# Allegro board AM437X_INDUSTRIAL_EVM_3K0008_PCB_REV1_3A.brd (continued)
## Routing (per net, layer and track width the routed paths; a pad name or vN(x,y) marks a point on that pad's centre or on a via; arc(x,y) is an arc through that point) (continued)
VDD_CORE: length 131.7
  TOP w0.203: v1(84.79,65.6) 84.79,66.09 U11.W12 U11.W13
  TOP w0.254: U11.N16 U11.N17 U11.P17 81.13,69.75 v1(81.61,69.27) 81.44,69.1 U11.P16 ; U11.M14 U11.L14 79.19,67.5 v1(79.36,67.32) ; v1(79.36,65.37) 79.36,65.02 U11.M9 U11.N9 ; U11.M12 U11.L12 78.85,66.83 v1(78.85,66.89) ; v1(82.61,65.37) 82.61,65.68 U11.T11 U11.R11 ; U11.R14 81.78,67.74 v1(82.13,67.39) 82.43,67.7 U11.T14 U11.U15 U11.V15 ; U11.R9 81.78,64.69 v1(82.11,65.02) 82.43,64.69 U11.T9 ; U11.T18 U11.T19 82.23,71.05 v1(82,71.28) ; U11.J11 77.89,65.85 v1(78.36,65.37) 78.19,65.2 U11.J10
  TOP w0.508: v3(107.53,64.23) R139.2 v3(106.53,65.28)
  L5_PWR w0.508: v1(79.36,67.32) 78.93,66.89 v1(78.85,66.89)
  BOTTOM w0.381: C213.1 80.23,68.37 79.55,67.69 79.55,67.51 v1(79.36,67.32) ; C221.1 84.79,66.46 v1(84.79,65.6) 84.84,65.56 84.84,65.48 85.55,64.77 85.72,64.77 ; C202.1 82.77,71.28 v1(82,71.28) ; v1(82.61,65.37) 82.61,66.04 C224.1 ; v1(78.36,65.37) 78.36,65.78 C219.1 ; v1(78.85,66.89) 79.36,66.39 C220.1
  BOTTOM w0.508: v1(81.61,69.27) 81.61,69.27 C205.1 ; v3(94.2,56.64) 95.14,56.64 C257.1 94.63,57.66 v3(94.23,57.66)
  BOTTOM w0.762: v3(106.53,65.28) 105.35,64.1 105.35,60.39 105.79,59.94 105.79,54.74 104.9,53.85 104.9,50.67 v4(106.3,49.28) ; v4(106.33,45.72) 106.33,41.53 107.82,40.04 107.82,22.23 102.23,16.64 102.23,13.55 100.49,11.81 91.95,11.81 90.07,13.69 88.87,13.69 87.86,12.67 73.24,12.67 70.93,14.99 v3(58.12,14.99) v3(56.95,14.99)
  vias: v4(104.52,49.28) v4(104.52,47.5) v4(104.55,45.72) v4(106.3,47.5)
VDD_CORE_EN: length 86.1
  TOP w0.13: v1(107.95,43.81) 107.95,20.37 106.12,18.54 v1(106.08,18.54) ; R234.1 67.57,11.05 v1(66.67,11.95) U26.17
  L3_SIG1 w0.13: v1(107.95,43.81) 107.95,43.94 108.83,44.82 111.88,44.82 v1(115.19,48.13)
  BOTTOM w0.13: v1(115.19,48.13) 115.19,49.78 R482.2 ; v1(106.08,18.54) 103.96,16.42 103.96,14.11 100.79,10.94 98.51,10.94 97.68,10.11 91.01,10.11 89.47,11.65 83.22,11.65 81.68,10.11 72.29,10.11 70.45,11.95 v1(66.67,11.95)
VDD_COREREG: length 4.8
  BOTTOM w0.203: 115.82,46.36 U53.A2 U53.B2 115.82,46.86
VDD_MPU: length 141.2
  TOP w0.203: U11.M18 79.55,70.68 79.55,71.28
  TOP w0.254: v1(78.36,67.32) 78.19,67.15 U11.J13 U11.J14 U11.H14 U11.H13 ; v1(78.06,71.73) 78.51,71.73 U11.K20 U11.L20 79.2,71.7 v1(79.59,71.31) 79.32,71.05 U11.L19 U11.K19 ; U11.M17 U11.M18 ; U11.H16 U11.J16 78.19,69.1 v1(78.37,68.93)
  TOP w0.508: R230.2 56.78,11.68 55.98,12.48 55.98,17.31 58.49,19.81 63.37,19.81 64.64,21.08 64.64,23.8 64.19,24.25 64.19,25.73 v3(64.69,26.24)
  L3_SIG1 w0.508: v3(64.69,26.24) 67.26,23.67 67.26,23.67 69.59,21.34 72.01,21.34 72.95,22.28 73.82,22.28 74.83,21.26 75.72,21.26 76.79,20.19 77.24,20.19 77.42,20.02 78.72,20.02 80.06,18.67 82.99,18.67 84.21,19.89 93.17,19.89 93.47,20.19 93.47,21.37 96.49,24.38 96.74,24.64 96.74,24.64 96.87,24.77 99.95,24.77 102.2,27.02 102.2,32.48 101.46,33.23 101.46,38.45 100.81,39.09 100.81,50 96.46,54.36 95.17,54.36 93.28,56.24 93.28,58.23 91.47,60.05 89.92,60.05 88.87,61.09 88.87,61.57 85.65,64.79 83.87,64.79 83.44,65.23 83.44,67.46 82.72,68.18 78.92,68.18 78.36,67.62 v1(78.36,67.32)
  L5_PWR w0.508: 94.7,82.76 TP7.1 96.31,82.76
  BOTTOM w0.381: C197.1 78.59,72.1 78.22,71.73 v1(78.06,71.73) ; C203.1 79.21,71.31 v1(79.59,71.31) ; v1(78.37,68.93) 78.37,69.1 77.87,69.6 C207.1
  BOTTOM w0.508: v3(88.75,82.6) 88.75,83.48 C172.1 87.91,83.35 v3(87.91,82.63)
  vias: v3(64.82,27.13) v4(93.85,87.5) v4(93.85,85.72) v4(95.5,85.72) v4(97.16,87.5) v4(97.16,85.72)
VDD_MPU_EN: length 203.1
  TOP w0.13: U26.18 66.12,12.45 67.01,13.34 R228.1 67.69,13.27 68.39,12.57 69.04,12.57 69.55,13.08 v1(69.93,13.08) ; v1(104.23,98.14) v1(104.23,105.12)
  L3_SIG1 w0.13: v1(136.91,52.45) 136.91,50.72 136.58,50.4 136.58,40.82 131.84,36.08 127.43,36.08 124.12,39.38 121.22,39.38 120.76,38.93 120.76,36 119.87,35.11 119.87,34.28 119,33.42 117.66,33.42 117.21,32.96 117.21,31.9 110.33,25.02 110.33,23.13 108.12,20.92 108.12,17.97 104.41,14.26 104.41,11.37 102.61,9.57 100.37,9.57 100.04,9.24 96.31,9.24 95.66,8.59 91.51,8.59 90.85,9.25 78.51,9.25 74.93,12.83 70.18,12.83 v1(69.93,13.08) ; v1(104.23,105.12) 104.9,105.79 117.23,105.79 117.62,106.18 121.34,106.18 122.1,106.93 129.16,106.93 131.19,104.9 131.19,103.84 136.03,99 136.03,94.61 136.46,94.18 136.46,89.88 134.4,87.83 134.4,87.21 134.67,86.94 134.67,86.1 136.27,84.5 v1(136.27,73.53)
  L4_SIG2 w0.13: v1(136.27,73.53) 136.27,73.15 135.36,72.24 135.36,70.55 136.4,69.52 136.4,58.85 137.19,58.06 137.19,52.73 v1(136.91,52.45)
  BOTTOM w0.13: R324.2 v1(104.23,98.14)
VDD_MPU_OUT: length 2.3
  BOTTOM w0.254: U35.B3 U35.B4 100.71,93.43
  BOTTOM w0.381: 99.41,93.57 99.54,93.43 100.71,93.43
VDD_MPU_SENSE: length 2.5
  TOP w0.508: R52.1 96.77,90.68 v3(97.28,90.17)
VDD_MPU_SENSEP: length 7.7
  TOP w0.508: v1(103.59,93.43) 96.81,93.43 R52.2
  BOTTOM w0.254: 103,93.43 U35.B1
  BOTTOM w0.381: v1(103.59,93.43) 103,93.43
VDD_TAMPER: length 17.7
  TOP w0.13: U11.AD9 87.94,64.86 88.73,64.86
  TOP w0.508: R139.1 104.48,63.97 C60.1 96.07,63.97 95.42,64.63 90.17,64.63 89.94,64.86 88.73,64.86
VDDA1P8_PMLDO: length 3.7
  TOP w0.254: U11.D6 v1(74.48,62.11)
  BOTTOM w0.381: v1(74.48,62.11) 74.03,62.11 74.03,62.11 73.54,62.11 73.28,61.85 R463.1
VDDA3P3_PMLDO: length 5.5
  TOP w0.254: v1(75.93,64.38) 75.94,64.38 U11.F8
  BOTTOM w0.381: R456.1 71.96,63.81 75.25,63.81 75.62,64.19 75.63,64.19 75.83,64.38 v1(75.93,64.38)
VDDA_ADC: length 13
  TOP w0.254: v1(86.65,65.59) 86.65,66.19 U11.AB12
  BOTTOM w0.508: 88.04,67.15 88.04,66.33 87.31,65.59 v1(86.65,65.59) ; 88.04,67.15 93.25,67.15 94.74,65.66 FB14.1 ; 88.04,67.15 88.01,67.18
VDDA_MC_ADC: length 19.5
  TOP w0.13: v1(84.7,69.45) 84.7,69.43 84.74,69.39 84.74,69.39 U11.Y16
  L3_SIG1 w0.254: 89.03,69.6 88.14,68.71 85.41,68.71 84.7,69.42 v1(84.7,69.45)
  L3_SIG1 w0.508: 89.03,69.6 89.66,70.23 94.74,70.23 95.89,71.37 100.86,71.37 v3(101.32,71.83)
  BOTTOM w0.381: v1(84.7,69.45) 84.81,69.34 84.81,69.22 85.14,68.89 C211.1
VDDR_VREF: length 58.2
  TOP w0.203: U20.M8 76.06,31.61 75.69,31.24 75.07,31.24 74.69,30.86 74.32,30.86 v1(73.85,30.4)
  TOP w0.254: U21.M8 v1(94.33,31.22)
  TOP w0.305: U25.6 92.1,12.6
  TOP w0.381: U21.H1 87.65,34.82 87.18,34.34 v1(87.18,32.87) ; U20.H1 69.98,34.82
  TOP w0.508: 69.98,34.82 69.49,34.82 v1(69.09,34.42) v1(68.58,33.91)
  L4_SIG2 w0.508: 95.38,26.8 95.38,25.91 92.2,22.73 82.22,22.73 81.58,23.37 80.98,23.37 80.34,22.73 78.89,22.73 v3(78.18,23.44) v3(76.96,23.44)
  BOTTOM w0.508: v1(87.18,32.87) 86.43,32.13 C311.1 86.3,32.07 86.3,31.79 85.36,30.85 ; C317.2 94.33,30.51 v1(94.33,31.22) 94.33,31.97 C312.1 ; C330.1 73.85,27.21 v1(73.85,30.4) ; v1(68.58,33.91) 68.2,33.53 C307.1 C313.2
  BOTTOM w0.762: 74.42,25.91 70.99,25.91 69.39,27.51 ; 75.18,27.05 79.76,27.05 83.55,30.85 85.36,30.85
VDDR_VTT: length 9.5
  TOP w0.254: U25.3 93.85,16.76 C106.1
  TOP w0.508: R225.2 88.65,16.89 88.14,17.4 88.14,21.35 v3(88.15,21.36) ; C106.1 93.34,18.53 C104.1
  vias: v3(85.61,21.41) v3(86.89,21.36) v3(89.64,21.32) v3(90.92,21.32) v3(92.08,21.34)
VDDS_CTM: length 9.6
  TOP w0.13: 88.79,66.18 87.96,66.18 U11.AD12
  TOP w0.508: 88.79,66.18 89.31,65.66 FB6.1
VDDS_DDR: length 89.9
  TOP w0.203: v1(70.86,32.83) 70.88,32.83 U20.K2
  TOP w0.254: v1(69.73,29.37) 70,29.11 70.35,29.11 U20.R1 ; v1(88.62,39.19) 88.75,39.19 U21.C1 89.28,38.66 89.28,38.44 89.7,38.02 U21.D2 ; v1(96.27,34.42) 95.87,34.82 U21.H9 ; v1(76.43,33.58) 76.41,33.58 76.06,33.23 U20.K8 ; U20.R9 77.21,29.22 77.41,29.41 v1(77.44,29.41) ; v1(69.91,30.91) 70.37,30.91 U20.N1 ; U21.E9 95.65,37.33 95.98,37.33 v1(96.09,37.44) ; U20.E9 77.3,37.22 v1(77.36,37.16) ; U20.F1 70.34,36.3 69.91,36.3 69.85,36.36 v1(69.84,36.36) ; U21.F1 v1(88.62,36.42) ; U21.D9 95.98,38.02 v1(96.08,38.12) ; U21.A8 v1(95.13,40.82) ; U21.A1 v1(88.62,40.42) ; U20.H2 v1(70.86,34.42) ; v1(76.05,40.95) 76.06,40.93 U20.A8 ; U21.G7 v1(93.29,35.62) ; v1(96.07,28.47) 96.07,28.68 U21.R9 ; v1(76.44,39.26) 76.44,39.24 U20.C9 ; U20.G7 74.92,35.27 74.92,35.18 v1(74.85,35.12) ; U21.K2 89.97,33.22 90.31,32.88 v1(90.31,32.88) ; C107.1 94.35,16.88 U25.2 ; v1(69.66,38.96) 69.81,38.82 U20.C1 70.46,38.63 71.08,38.02 U20.D2 ; U20.B2 70.92,39.95 70.85,39.95 v1(70.85,39.96) ; U20.N9 76.94,30.82 77.03,30.91 77.73,30.91 v1(78.08,31.27) ; U21.B2 v1(90.33,40.02) ; U21.N9 95.64,30.71 v1(96.42,30.71) ; v1(77.36,37.96) 77.3,38.02 U20.D9 ; v1(89.62,35.21) 89.62,35.13 U21.H2 ; U20.A1 v1(70.46,40.98) ; U21.C9 v1(96.72,38.82) ; v1(77.37,34.82) 77.37,34.82 U20.H9 ; U21.K8 v1(94.33,32.82)
  TOP w0.381: v3(65.37,44.58) 65.37,44.18
  TOP w0.457: 65.37,44.18 65.91,43.63
  TOP w0.508: 65.91,43.63 C80.1 64.88,43.16 v3(63.9,42.18) ; v3(95.63,20.32) 98.3,20.32 99.06,19.56 99.06,15.49 98.17,14.61 R226.2 C111.1 ; v3(82.68,23.93) C102.1 v3(81.28,22.59)
  L3_SIG1 w0.508: 76.07,32.77 75.66,32.35 72.33,32.35 71.84,32.83 v1(70.86,32.83) ; v1(78.08,31.27) 78.08,32.03 77.98,32.13
  L4_SIG2 w0.508: v1(77.44,29.41) 78.08,30.05 v1(78.08,31.27)
  BOTTOM w0.381: C302.1 70.86,35.06 v1(70.86,34.42) ; v1(74.85,35.12) 75.06,35.32 C299.1 ; v1(96.27,34.42) 96.14,34.54 C301.1 ; C317.1 95.76,30.48 95.99,30.71 v1(96.42,30.71) 96.58,30.86 C318.1 ; v1(88.62,28.3) 88.73,28.3 88.95,28.51 89.09,28.51 C328.1 ; C283.1 88.34,40.64 88.56,40.42 v1(88.62,40.42) ; v1(77.36,37.96) 77.1,37.96 76.71,38.35 C288.1 ; C285.1 76,39.61 76.34,39.26 v1(76.44,39.26) ; 69.09,30.86 69.14,30.91 v1(69.91,30.91) ; v1(96.09,37.44) 96.09,37.32 96.45,36.96 C296.1 ; C292.1 70.09,38.24 70.09,38.27 69.66,38.7 v1(69.66,38.96) 69.33,38.96 69.3,38.99 68.71,38.99 ; v1(69.73,29.37) 69.67,29.31 69.12,29.31 C324.1 ; v1(69.84,36.36) 69.78,36.3 69.7,36.3 69.22,35.81 C297.1 ; C294.1 89.43,36.42 v1(88.62,36.42)
  BOTTOM w0.508: C279.1 68.73,41.27 68.82,41.18 70.26,41.18 v1(70.46,40.98) ; C313.1 68.58,30.86 69.09,30.86 ; C329.1 96.39,27.3 96.39,27.81 96.07,28.14 v1(96.07,28.47) ; v1(77.36,37.16) 77.08,36.88 C295.1 ; v1(95.13,40.82) 94.83,40.51 C284.1 ; C318.1 97.69,31.39 100.74,31.39 101.85,32.51 C306.2 ; C290.1 95.49,38.12 v1(96.08,38.12) 96.76,38.12 C291.1 ; C277.1 75.95,41.05 v1(76.05,40.95) ; C282.1 96.9,39.43 96.72,39.25 v1(96.72,38.82) ; C323.1 77.55,29.34 77.47,29.41 v1(77.44,29.41) ; C316.1 87.79,30.1 88.28,30.58 88.28,30.6 v1(88.27,30.61) ; C314.1 90.3,32.26 90.3,32.87 v1(90.31,32.88) ; v1(70.86,34.42) v1(70.86,32.83) 70.84,32.83 69.77,33.91 C304.1 ; C278.1 90.17,40.18 v1(90.33,40.02)
  vias: v3(64.01,38.86) v3(64.01,37.59) v3(64.01,36.32) v3(64.01,35.05) v3(65.28,38.86) v3(65.28,37.59) v3(65.28,36.32) v3(65.28,35.05) v3(94.61,21.21) v3(94.61,20.19) v3(95.63,21.21)
VDDS_TAMPER: length 17.6
  TOP w0.13: 88.9,63.59 87.94,63.59 U11.AD8
  TOP w0.508: 88.9,63.59 95.19,63.59 95.95,62.83 C62.1 104.48,62.83 R142.1
ADC0_VREFP: length 11.7
  TOP w0.13: U11.AD14 87.94,67.49 89.99,67.49 90.55,66.93 94.4,66.93 95.44,67.96 95.78,67.96 C56.1 C57.1 R126.2
ADC1_VREFP: length 13.8
  TOP w0.13: U11.AE15 93.88,68.45 95.54,70.11 95.92,70.11 96.98,71.16 97.62,71.16 C54.1 C55.1 R110.2
AM437X_AIN0: length 66.2
  TOP w0.13: v1(108.97,75.18) 109.62,74.53 109.62,73.37 109.09,72.84 108.83,72.84 107.98,71.99 107.98,68.83 105.25,66.11 103.32,66.11 v1(103.25,66.04)
  L4_SIG2 w0.13: v1(108.97,75.18) 106.2,75.18 105.5,75.89 105.5,77.81 105.95,78.26 105.95,80.91 106.71,81.67 110.48,81.67 111.05,82.24 112.15,82.24 112.47,82.55 112.47,86.35 111.81,87.01 111.81,89.06 110.72,90.14 110.72,91.07 109.27,92.53 108.23,92.53 106.87,93.89 106.87,101.31 108.33,102.77 108.33,109.05 108.89,109.61 108.89,111.23 107.82,112.29 J1.31
  BOTTOM w0.13: R450.1 v1(103.25,66.04)
AM437X_AIN1: length 62.1
  BOTTOM w0.13: J1.33 113.14,111.46 118.34,111.46 119.25,110.54 119.25,109.58 119.43,109.4 119.43,106.61 119.1,106.28 119.1,105.39 118.11,104.4 118.11,97.95 116.97,96.8 116.97,93.22 116.33,92.58 112.95,92.58 111.28,90.91 111.28,88.77 110.52,88.01 109.78,88.01 107.54,85.77 107.54,83.11 108.74,81.91 109.98,81.91 110.84,81.05 110.84,75.92 110.54,75.62 110.54,71.36 109.55,70.36 R440.1
AM437X_AIN2: length 50.4
  L3_SIG1 w0.13: v1(106.4,74.17) 105.41,75.16 105.41,79.02 106.48,80.09 v1(107.29,80.09)
  L4_SIG2 w0.13: J1.35 112.9,112.74 111.49,111.33 111.49,109.46 110.84,108.81 110.84,103.63 110.54,103.33 110.54,98.27 110.26,97.99 110.26,94.47 111.65,93.08 111.65,90.52 112.73,89.44 112.73,87.39 113.39,86.73 113.39,81.13 112.79,80.53 107.74,80.53 v1(107.29,80.09)
  BOTTOM w0.13: 107.06,73.91 106.81,74.17 v1(106.4,74.17)
AM437X_AIN3: length 52.6
  L3_SIG1 w0.13: v2(106.3,72.77) 107.19,73.66 107.19,76.42 105.83,77.78 105.83,78.36 107.07,79.6 109.02,79.6 109.25,79.38 v1(109.93,79.38)
  L4_SIG2 w0.13: v1(109.93,79.38) 112.78,79.38 114.23,80.83 114.23,86.76 113.35,87.65 113.35,89.46 113.67,89.78 113.67,90.42 113.37,90.72 113.37,94.53 112.83,95.07 112.83,99.46 112.42,99.88 112.42,107.08 114.09,108.76 114.09,110.92 115.44,112.27 J1.37
  BOTTOM w0.13: 107.06,72.77 v2(106.3,72.77)
AM437X_AIN4: length 55.1
  TOP w0.13: v1(105.94,76.5) 105.94,76.16 105.66,75.88 105.66,72.64 105.92,72.39 105.92,71.75 105.28,71.12
  L4_SIG2 w0.13: J1.32 109.01,115.59 109.01,112 109.3,111.71 109.3,109.57 108.64,108.92 108.64,102.64 108.36,102.36 108.36,96.32 108.47,96.21 108.47,93.76 111.03,91.2 111.03,90.27 112.11,89.19 112.11,87.14 112.78,86.47 112.78,82.42 112.28,81.93 111.17,81.93 110.6,81.36 106.84,81.36 106.26,80.78 106.26,79.63 106.74,79.15 106.74,78.1 106.79,78.05 106.79,77.36 v1(105.94,76.5)
AM437X_AIN5: length 53.8
  TOP w0.13: v1(106.71,80.59) 106.71,79.2 105.28,77.77 105.28,72.14 ; v1(110.23,107.95) 109.32,108.86 109.32,110.54 109.32,110.54 109.32,115.73 J1.34
  L4_SIG2 w0.13: v1(106.71,80.59) 107.02,80.91 112.53,80.91 113.08,81.46 113.08,86.6 112.42,87.26 112.42,89.31 111.34,90.39 111.34,91.76 109.95,93.15 109.95,98.53 109.37,99.11 109.37,101.88 110.23,102.73 v1(110.23,107.95)
AM437X_AIN6: length 61.4
  TOP w0.13: v1(108.03,80.09) 108.46,79.65 108.46,78.87 107.5,77.91 107.5,76.01 109.31,74.2 109.31,73.5 108.96,73.15 108.66,73.15 107.59,72.09 107.59,68.89 106.02,67.31 105.28,67.31
  L4_SIG2 w0.13: v1(108.03,80.09) 112.98,80.09 113.7,80.81 113.7,86.86 113.04,87.52 113.04,89.57 112.75,89.86 112.75,90.23 113.03,90.51 113.03,94 110.85,96.18 110.85,103.21 111.15,103.51 111.15,108.68 111.86,109.39 111.86,111.26 113.88,113.28 113.88,115.79 J1.36
AM437X_AIN7: length 58
  TOP w0.13: 105.28,68.58 105.98,69.28 106.23,69.28 106.49,69.54 106.49,70.5 106.75,70.76 106.75,72.55 107,72.8 107,76.01 106.81,76.2 106.81,77.9 v1(107.19,78.28)
  L4_SIG2 w0.13: v1(107.19,78.28) 107.65,78.28 108.19,78.83 112.74,78.83 114.54,80.63 114.54,91.98 114.37,92.16 114.37,93.98 113.14,95.2 113.14,99.59 112.72,100.01 112.72,106.93 114.4,108.61 114.4,110.78 116.42,112.8 116.42,115.79 J1.38
AM437X_CAM0_DATA0: length 145.3
  TOP w0.13: v1(97.97,78) 96.59,76.62 96.59,73.98 95.12,72.52 95.12,72.23 93.29,70.4 U11.AE18 ; v1(122.55,9.4) R264.2
  L3_SIG1 w0.13: v1(114.35,95.17) 111.51,92.33 109.35,92.33 108.77,91.75 108.77,89.63 109.63,88.77 109.63,87.87 104.79,83.04 104.63,83.04 104.07,83.59 103.91,83.59 103.8,83.48 103.8,83.32 104.35,82.76 104.35,82.6 104.24,82.48 104.08,82.48 103.52,83.04 103.36,83.04 103.24,82.92 103.24,82.76 103.8,82.21 103.8,82.05 103.68,81.93 103.52,81.93 102.97,82.49 102.81,82.49 102.69,82.37 102.69,82.21 103.25,81.65 103.25,81.49 103.13,81.38 102.97,81.38 102.41,81.93 102.25,81.93 102.14,81.82 102.14,81.66 102.69,81.1 102.69,80.94 101.38,79.63 101.38,79.28 100.83,78.73 98.7,78.73 v1(97.97,78)
  L4_SIG2 w0.13: v1(122.55,9.4) 122.08,9.87 120.33,9.87 119,8.54 115.28,8.54 111.56,12.26 111.56,16.53 112.69,17.65 114.06,17.65 115.32,18.91 115.32,24.18 117.22,26.08 117.22,28.55 117.22,28.55 117.22,29.68 117.22,29.68 117.22,33.7 116.97,33.95 116.11,34.81 116.11,38.1 114.83,39.37 114.83,44.26 114.48,44.62 114.48,50.65 114.65,50.82 114.65,51.89 113.68,52.85 113.68,55.8 114.35,56.46 114.35,59.38 110.41,63.32 108.25,63.32 107.87,63.71 106.68,63.71 106.2,64.19 105.5,64.88 103.74,64.88 100.76,67.87 100.3,67.87 99.69,68.48 99.69,69.39 100,69.7 100,74.29 99.46,74.84 99.46,76.51 v1(97.97,78)
  BOTTOM w0.13: R326.2 114.68,95.5 v1(114.35,95.17)
AM437X_CAM0_DATA1: length 192.3
  TOP w0.13: U11.AB18 v1(86.33,69.93) ; v1(112.14,12.57) 107.06,12.57 105.28,10.79 R253.2
  L3_SIG1 w0.13: v1(86.33,69.93) 89.18,72.77 91.28,72.77 92.18,73.67 93.5,73.67 95.47,75.63 95.47,80.25 96.58,81.37 97.62,81.37 98.17,81.91 100.71,81.91 101.2,82.41 101.2,82.57 100.92,82.85 100.92,83.01 101.04,83.13 101.2,83.13 101.48,82.85 101.64,82.85 101.76,82.96 101.76,83.12 101.47,83.41 101.47,83.57 101.59,83.68 101.75,83.68 102.03,83.4 102.2,83.4 107.09,88.29 v1(109.12,88.29)
  L4_SIG2 w0.13: v1(112.14,12.57) 113.47,13.9 116.53,13.9 121.88,19.26 121.88,26.39 125.53,30.03 125.53,39.04 124.55,40.02 124.55,45.16 124.19,45.52 124.19,47.5 125.85,49.16 125.85,58.75 123.11,61.49 123.11,65.54 119.27,69.38 116.11,69.38 113.61,71.88 v1(109.86,71.88)
  BOTTOM w0.13: R375.2 90.55,97.03 93.83,100.3 95.99,100.3 98.81,103.12 102.23,103.12 105.03,100.33 108.77,100.33 109.35,99.75 109.35,98.55 111.39,96.51 R327.2 112.9,93.15 110.57,90.81 110.57,89.39 109.89,88.71 109.54,88.71 v1(109.12,88.29) 109.12,87.97 107.1,85.95 107.1,82.91 108.56,81.46 109.68,81.46 110.41,80.73 110.41,76.1 110.11,75.8 110.11,72.14 v1(109.86,71.88)
AM437X_CAM0_DATA2: length 55.3
  TOP w0.13: v1(85.06,69.93) 85.03,69.95 U11.Y18 ; v1(113.23,101.73) 113.85,101.12 U6.5
  L3_SIG1 w0.13: v1(113.23,101.73) 112.98,101.47 108.33,101.47 102.87,96.01 102.87,93.6 102.72,93.45 102.39,93.45 102.23,93.3 102.23,93.08 102.39,92.93 102.72,92.93 102.87,92.77 102.87,92.56 102.72,92.41 102.39,92.41 102.23,92.25 102.23,92.04 102.39,91.88 102.72,91.88 102.87,91.73 102.87,91.52 102.72,91.36 102.39,91.36 102.23,91.21 102.23,90.99 102.39,90.84 102.72,90.84 102.87,90.69 102.87,89.92 96.61,83.66 96.61,82.63 94.55,80.57 94.55,75.95 93.16,74.56 91.84,74.56 91.07,73.79 88.91,73.79 v1(85.06,69.93)
AM437X_CAM0_DATA3: length 55.7
  TOP w0.13: v1(85.68,69.93) U11.AA18 ; U6.6 v1(113.2,100.2)
  L3_SIG1 w0.13: v1(113.2,100.2) 112.56,100.84 108.31,100.84 106.68,99.21 106.68,95.38 105.79,94.49 105.25,94.49 104.27,93.5 104.27,90.68 103.93,90.34 103.93,90.12 104.46,89.59 104.46,89.37 104.31,89.22 104.09,89.22 103.56,89.75 103.34,89.75 103.19,89.6 103.19,89.38 103.72,88.85 103.72,88.63 103.57,88.48 103.35,88.48 102.82,89.01 102.6,89.01 99.76,86.17 99.76,84.9 98.12,83.26 97.9,83.26 97.61,83.55 97.39,83.55 97.24,83.4 97.24,83.18 97.79,82.63 97.79,82.17 97.42,81.8 96.4,81.8 94.99,80.39 94.99,75.77 93.33,74.12 92.01,74.12 91.17,73.28 89.03,73.28 v1(85.68,69.93)
AM437X_CAM0_DATA4: length 56.4
  TOP w0.13: v1(111.89,100.08) 112.54,99.42 U6.7 ; v1(103.12,85.34) 101.47,85.34 101.09,84.96 101.09,84.75 101.57,84.26 101.57,84.05 101.42,83.9 101.21,83.9 100.72,84.38 100.51,84.38 100.35,84.23 100.35,84.01 100.84,83.53 100.84,83.31 100.68,83.16 100.47,83.16 99.99,83.64 99.77,83.64 99.5,83.37 99.5,82.36 96.86,79.72 96.86,78.13 95.72,76.98 95.72,74.34 94.59,73.22 94.59,72.44 93.21,71.05 U11.AE19
  L3_SIG1 w0.13: v1(103.12,85.34) 104.16,86.38 104.16,88.45 104.89,89.19 104.89,90.67 105.35,91.12 105.56,91.12 105.92,90.77 106.13,90.77 106.29,90.92 106.29,91.13 105.93,91.49 105.93,91.71 106.55,92.33 106.55,94.36 107.15,94.96 108.29,94.96 108.71,95.38 108.71,97.17 108.6,97.28 108.06,97.28 107.95,97.4 107.95,97.56 108.06,97.67 108.6,97.67 108.71,97.79 108.71,97.95 108.6,98.06 108.06,98.06 107.95,98.18 107.95,98.34 108.06,98.45 108.6,98.45 108.71,98.57 108.71,98.73 108.6,98.84 108.06,98.84 107.95,98.96 107.95,99.12 108.06,99.24 108.6,99.24 108.71,99.35 108.71,99.69 109.09,100.08 v1(111.89,100.08)
  BOTTOM w0.13: R364.1 v1(103.12,85.34)
AM437X_CAM0_DATA5: length 57
  TOP w0.13: U11.AD19 87.98,70.71 93.25,70.71 94.82,72.28 94.82,72.83 96.15,74.16 96.15,76.8 97.3,77.95 97.3,79.54 98.91,81.15 101.22,81.15 101.68,81.61 101.68,81.78 101.08,82.37 101.08,82.54 101.19,82.65 101.36,82.65 101.96,82.05 102.12,82.05 102.23,82.17 102.23,82.33 101.63,82.93 101.63,83.09 101.75,83.2 101.91,83.2 102.51,82.6 102.67,82.6 102.79,82.72 102.79,82.88 102.19,83.48 102.19,83.64 102.3,83.76 102.46,83.76 103.06,83.16 103.22,83.16 103.34,83.27 103.34,83.43 102.74,84.03 102.74,84.2 102.85,84.31 103.02,84.31 103.62,83.71 103.78,83.71 103.89,83.83 103.89,83.99 103.29,84.59 103.29,84.75 103.41,84.86 103.57,84.86 104.17,84.26 104.33,84.26 104.65,84.58 v1(105.54,84.58) 106.07,85.11 106.07,85.28 105.28,86.07 105.28,86.23 105.39,86.34 105.56,86.34 106.35,85.55 106.51,85.55 107.51,86.55 107.51,86.71 107.03,87.19 107.03,87.35 107.15,87.46 107.31,87.46 107.78,86.99 107.94,86.99 108.51,87.55 108.51,89.33 108.71,89.53 108.71,93.34 111.89,96.52 111.89,98.16 U6.8
  BOTTOM w0.13: v1(105.54,84.58) R363.1
AM437X_CAM0_DATA6: length 149.5
  TOP w0.13: R247.2 v1(86.23,10.54) ; U11.AE20 93.07,71.7 93.58,72.21 v1(93.58,72.52) 94.13,73.07 94.13,73.7 94.9,74.47 94.9,78.47 99.06,82.63 99.06,83.07 98.17,83.96 98.17,84.18 98.32,84.33 98.54,84.33 99.01,83.86 99.23,83.86 99.6,84.24 99.6,84.45 99.11,84.95 99.11,85.17 99.26,85.32 99.48,85.32 99.97,84.82 100.19,84.82 100.34,84.97 100.34,85.19 99.85,85.69 99.85,85.9 100,86.05 100.21,86.06 100.71,85.56 100.93,85.56 101.08,85.71 101.08,85.93 100.58,86.42 100.58,86.64 100.73,86.79 100.95,86.79 101.45,86.3 101.66,86.3 101.82,86.45 101.82,86.66 101.32,87.16 101.32,87.38 101.9,87.96 102.54,87.96 102.69,88.11 102.69,88.75 102.84,88.9 103.06,88.9 103.21,88.75 103.21,88.11 103.36,87.96 103.75,87.96 103.9,88.11 103.9,88.75 104.05,88.9 104.27,88.9 104.42,88.75 104.42,88.11 104.57,87.96 104.79,87.96 104.94,88.11 104.94,88.75 105.1,88.9 105.31,88.9 105.46,88.75 105.46,88.11 105.62,87.96 106,87.96 107.4,89.36 107.4,90.63 107.55,90.79 108,90.79 108.15,90.94 108.15,91.15 108,91.31 107.55,91.31 107.4,91.46 107.4,91.68 107.55,91.83 108,91.83 108.15,91.98 108.15,92.2 108,92.35 107.55,92.35 107.4,92.5 107.4,92.72 107.55,92.87 108,92.87 108.15,93.02 108.15,93.4 111.24,96.49 U6.9
  L4_SIG2 w0.13: v1(93.58,72.52) 94.25,71.85 94.25,66.78 96.45,64.57 96.45,63.74 100.56,59.63 100.87,59.31 100.87,57.79 101.86,56.8 101.86,54.63 103.66,52.83 105.01,52.83 107.6,50.25 107.6,49.32 108.92,48 108.92,46.03 107.07,44.18 107.07,40.26 106.73,39.92 106.73,35.92 107.03,35.61 107.03,31.47 109.02,29.48 109.02,26.37 107.91,25.26 107.91,24.13 107.91,24.13 107.91,22.27 106.86,21.23 106.86,17.6 v1(106.25,16.98)
  BOTTOM w0.13: v1(86.23,10.54) 86.87,11.18 88.85,11.18 90.34,9.68 90.82,9.68 90.83,9.67 97.86,9.67 98.69,10.5 100.77,10.5 101.37,9.91 103.66,9.91 104.4,10.64 104.4,15.13 v1(106.25,16.98)
AM437X_CAM0_DATA7: length 55.8
  TOP w0.13: U11.AD20 87.94,72.01 92.91,72.01 93.16,72.25 93.16,72.69 93.9,73.43 93.9,73.79 94.67,74.57 94.67,78.96 97.63,81.91 97.63,84.55 98.36,85.28 98.36,86.74 98.51,86.89 99.44,86.89 99.59,87.04 99.59,87.26 99.44,87.41 98.51,87.41 98.36,87.56 98.36,87.78 98.51,87.93 99.44,87.93 99.59,88.08 99.59,88.3 99.44,88.45 98.51,88.45 98.36,88.6 98.36,88.9 99.12,89.66 101.47,89.66 101.62,89.81 101.62,90.53 101.78,90.68 101.99,90.68 102.15,90.53 102.15,89.81 102.3,89.66 102.51,89.66 102.67,89.81 102.67,90.53 102.82,90.68 103.04,90.68 103.19,90.53 103.19,89.81 103.34,89.66 103.56,89.66 103.71,89.81 103.71,90.53 103.86,90.68 104.08,90.68 104.23,90.53 104.23,89.81 104.38,89.66 104.77,89.66 105.28,90.17 105.28,90.38 104.77,90.89 104.77,91.1 104.93,91.26 105.14,91.26 105.65,90.75 105.86,90.75 106.02,90.9 106.02,91.12 105.51,91.62 105.51,91.84 105.66,91.99 105.88,91.99 106.38,91.49 106.6,91.49 106.97,91.85 106.97,94.53 107.4,94.96 109.1,94.96 110.59,96.46 U6.10
AM437X_CAM0_HSYNC: length 55.5
  TOP w0.13: v1(131.72,88.27) 130.56,87.1 125.48,87.1 124.62,86.25 117.26,86.25 115.71,84.7 115.66,84.7 115.33,84.36 113.17,84.36 111.4,86.14 108.36,86.14 105.68,83.46 104.97,83.46 100.8,79.28 99.29,77.78 99.1,77.78 97.71,76.39 97.46,76.13 97.46,73.56 95.36,71.47 95.12,71.47 93.41,69.75 U11.AE17
  BOTTOM w0.13: U38.7 v1(131.72,88.27)
AM437X_CAM0_PCLK: length 55.1
  TOP w0.13: U11.AC20 87.29,71.39 93.22,71.39 94.36,72.53 94.36,73.6 95.28,74.52 95.28,77.49 v1(96.01,78.21)
  L3_SIG1 w0.13: v1(96.01,78.21) 96.77,77.45 98.48,77.45 99.26,78.23 101.47,78.23 102.35,79.11 102.35,79.88 108.9,86.43 111.4,86.43 113.41,88.44 116.39,88.44 116.59,88.25 119.93,88.25 121.16,89.48 121.16,89.7 120.65,90.21 120.65,90.42 120.8,90.58 121.02,90.58 121.53,90.07 121.74,90.07 121.9,90.22 121.9,90.44 121.39,90.94 121.39,91.16 121.54,91.31 121.76,91.31 122.26,90.8 122.48,90.8 122.99,91.31 v1(124.33,91.31)
  BOTTOM w0.13: U34.3 125.33,92.31 v1(124.33,91.31)
AM437X_CAM0_VSYNC: length 58.4
  TOP w0.13: v1(132.37,90.93) 132.37,89.58 130.33,87.54 125.2,87.54 124.53,86.87 117.22,86.87 115.43,85.08 113.25,85.08 111.57,86.76 108.35,86.76 105.48,83.89 104.79,83.89 99.11,78.21 98.92,78.21 97.53,76.82 97.53,76.82 97.02,76.31 97.02,73.8 93.32,70.09 87.94,70.09 U11.AD18
  BOTTOM w0.13: U38.6 v1(132.37,90.93)
AM437X_CAM1_DATA2: length 122.6
  TOP w0.13: U11.AD21 87.94,72.66 92.47,72.66 93.43,73.62 93.43,73.99 94.19,74.74 94.19,79.96 94.13,80.01 94.13,81.4 93.35,82.19 93.35,83.57 v1(94.11,84.33)
  L4_SIG2 w0.13: v1(94.11,84.33) 94.73,84.95 94.73,85.99 94.22,86.5 91.43,86.5 90.7,87.22 90.7,92.43 89.28,93.85 83.74,93.85 81.03,96.57 81.03,104.92 80.4,105.55 77.11,105.55 75,107.66 67.7,107.66 67.22,107.18 61.76,107.18 57.74,103.15 51.71,103.15 51.65,103.22 43.59,103.22 42.58,102.21 30.73,102.21 28.74,104.2 27.3,104.2 25.38,106.12 v1(24.83,106.12)
  BOTTOM w0.13: v1(24.83,106.12) 24.57,106.37 24.57,109.03 24.26,109.35 20.32,109.35 19.69,109.98 19.69,111.76 20.07,112.14 20.7,112.14 R277.1
AM437X_CAM1_DATA3: length 85.8
  TOP w0.13: v1(106.43,10.79) 111.38,10.79 112.27,9.91 R258.2 ; U11.AE22 92.21,73 v1(92.39,73.18)
  L4_SIG2 w0.13: v1(106.43,10.79) 106.9,11.27 106.9,14.8 107.3,15.2 107.3,21.05 108.34,22.09 108.34,24.31 108.34,24.31 108.34,25.08 109.45,26.19 109.45,29.67 107.47,31.65 107.47,35.79 107.16,36.1 107.16,39.74 107.5,40.08 107.5,44 109.36,45.85 109.36,48.18 108.03,49.5 108.03,51.05 107.5,51.58 107.5,52.05 108.03,52.58 108.03,53.08 105.25,55.86 103.41,55.86 101.31,57.97 101.31,59.49 100.99,59.81 96.89,63.92 96.89,64.75 96.63,65.01 94.68,66.96 94.68,72.37 93.88,73.18 v1(92.39,73.18)
AM437X_CAM1_DATA5: length 87.3
  TOP w0.13: v1(108.08,9.4) R255.2 ; v1(93.33,76.69) 93.62,76.4 93.62,75.55 91.72,73.65 U11.AE23
  L4_SIG2 w0.13: v1(93.33,76.69) 93.76,76.26 95.78,74.23 95.78,68.28 97.81,66.26 97.81,64.3 101.34,60.77 102.12,60.77 103.31,59.58 103.31,57.98 103.7,57.59 104.83,57.59 105.52,56.9 109.44,52.98 109.44,49.4 110.43,48.41 110.43,45.1 110.72,44.81 110.72,43.12 110.06,42.46 110.06,41.33 108.08,39.35 108.08,36.75 108.39,36.44 108.39,32.25 110.38,30.27 110.38,25.81 109.27,24.7 109.27,21.7 108.22,20.66 108.22,14.82 107.82,14.42 107.82,10.16 108.08,9.91 v1(108.08,9.4)
AM437X_CAM1_DATA6: length 225.5
  TOP w0.13: v1(17.14,73.79) 18.03,74.68 21.46,74.68 24.89,78.11 v1(26.42,78.11) ; v1(91.44,82.8) 91.9,82.34 92.75,82.34 93.82,81.27 93.82,79.99 93.94,79.87 93.94,75.53 91.72,73.31 87.98,73.31 U11.AD23 ; v1(17.67,104.49) 17.67,104.48 18.4,103.76 24,103.76 28.35,108.11 44.75,108.11 45.56,108.92 45.56,111.76 44.71,112.6 44.71,116.79 45.95,118.03 54.39,118.03 v1(54.87,117.55)
  L3_SIG1 w0.13: v1(106.55,112.52) 106.55,114.68 105.79,115.44 69.36,115.44 69.23,115.57 69.22,115.57 68.51,116.27 68.51,116.28 66.76,118.03 62,118.03 59.98,116.01 56.41,116.01 v1(54.87,117.55) ; v1(17.67,104.49) 14.35,101.17 14.35,98.17 12.05,95.87 12.05,87.64 13.51,86.19 13.51,77.42 v1(17.14,73.79)
  L4_SIG2 w0.13: v1(106.55,112.52) 106.3,112.52 101.81,108.03 100.71,108.03 98.34,105.66 97.03,105.66 95.32,103.95 95.32,102.33 94.96,101.97 94.96,96.48 100.12,91.33 101.38,91.33 104.79,87.92 v1(104.79,87.25)
  BOTTOM w0.13: v1(17.14,73.79) 17.78,73.79 R431.2 ; R417.2 v1(26.42,78.11) ; v1(91.44,82.8) 91.62,82.99 93.96,82.99 94.74,82.21 96.04,82.21 97.27,83.44 103.62,83.44 104.79,84.61 v1(104.79,87.25)
AM437X_CAM1_DATA7: length 83.8
  TOP w0.13: v1(106.55,9.4) R254.2 ; v1(92.88,75.79) 92.88,75.78 91.35,74.25 88.33,74.25 U11.AE24
  L4_SIG2 w0.13: v1(92.88,75.79) 95.3,73.37 95.3,68.33 97.5,66.13 97.5,64.17 101.61,60.07 101.92,59.75 101.92,58.37 103.7,56.59 105.39,56.59 109.13,52.86 109.13,49.27 109.97,48.43 109.97,44.56 109.66,44.25 109.66,41.37 107.78,39.48 107.78,36.54 108.08,36.24 108.08,31.98 110.07,30 110.07,25.93 108.96,24.82 108.96,21.83 107.92,20.79 107.92,14.95 107.52,14.55 107.52,10.36 v1(106.55,9.4)
AM437X_CAM1_DATA8: length 115.1
  TOP w0.13: v1(124.59,9.4) R265.2 ; U11.AD24 87.98,73.96 91.64,73.96 93.31,75.62 93.31,76.04 92.91,76.43 v1(92.91,77.76) 92.91,80.13 90.92,82.12 90.92,83.04 91.69,83.82 R80.1
  L4_SIG2 w0.13: v1(92.91,77.76) 96.09,74.58 96.09,68.41 98.12,66.39 98.12,64.43 101.47,61.08 103.52,61.08 104.64,59.95 104.64,59.31 107.02,56.93 107.02,55.83 109.75,53.11 109.75,49.53 110.74,48.54 110.74,45.23 111.03,44.94 111.03,43 110.37,42.34 110.37,41.2 108.39,39.23 108.39,37.74 108.73,37.4 109.18,37.4 109.66,36.91 109.66,31.42 110.68,30.4 110.68,30.14 110.68,25.68 109.57,24.57 109.57,21.58 108.53,20.54 108.53,14.69 108.13,14.29 108.13,10.61 v1(108.46,10.29)
  BOTTOM w0.13: v1(108.46,10.29) 109.82,8.93 124.12,8.93 v1(124.59,9.4)
AM437X_CAM1_WEN: length 105.9
  TOP w0.13: U11.AB25 86.33,75.06 86.25,75.14 86.25,77.77 87.54,79.06 87.54,81.37 86.51,82.4 86.51,90.4 85.98,90.93 85.98,94.49 v1(86.61,95.12)
  L4_SIG2 w0.13: v1(25.33,106.6) 27.42,104.51 28.86,104.51 30.86,102.51 42.24,102.51 43.37,103.64 56.17,103.64 61.23,108.7 74.41,108.7 77.25,105.86 80.34,105.86 80.59,105.86 81.33,105.12 81.33,96.69 83.03,95 86.48,95 v1(86.61,95.12)
  BOTTOM w0.13: R275.1 24.13,112.01 23.56,112.01 23.18,111.63 23.18,110.43 23.75,109.86 24.64,109.86 25.05,109.44 25.05,106.89 v1(25.33,106.6)
AM437X_DCAN0_RX: length 12.4
  TOP w0.13: v1(79.67,73.01) 79.65,73 79.31,73 U11.L22
  BOTTOM w0.13: v1(79.67,73.01) 79.67,73.13 79.3,73.49 79.3,79.96 78.74,80.52 78.74,81.67 78.33,82.09 78.33,82.65 R386.1 C176.1
AM437X_DCAN0_TX: length 11
  TOP w0.13: v1(78,73.42) 78.42,73 U11.K22
  BOTTOM w0.13: R387.1 77.09,81.91 77.69,81.31 77.69,80.18 77.85,80.03 77.85,79.55 77.87,79.53 77.87,77.13 77.58,76.85 77.58,75.33 78.09,74.82 78.09,74.05 78.09,74.05 78.09,73.7 78,73.61 v1(78,73.42)
AM437X_EHRPWM0_SYNCI: length 118
  TOP w0.13: U11.P25 81.13,75.14 81.8,75.81 81.8,78.38 82.03,78.6 82.03,79.55 82.38,79.9 82.38,81.04 82.8,81.46 v1(82.8,81.64)
  L4_SIG2 w0.13: v1(105.92,14.22) 105.61,14.53 105.61,18.74 106.43,19.56 106.43,21.41 107.47,22.45 107.47,23.95 107.47,25.44 108.58,26.55 108.58,29.3 106.6,31.29 106.6,35.43 106.29,35.74 106.29,40.1 106.63,40.44 106.63,44.36 107.11,44.84 107.11,49.56 106.62,50.05 106.5,50.05 104.16,52.4 103.84,52.4 103.48,52.4 101.37,54.5 101.37,56.67 100.44,57.61 100.44,59.13 100.12,59.45 96.02,63.56 96.02,64.39 93.81,66.6 93.81,70.91 91.92,72.8 91.92,78.57 90.6,79.88 87.96,79.88 87.31,79.23 85.74,79.23 85.4,79.57 84.87,79.57 v1(82.8,81.64)
  BOTTOM w0.13: v1(105.92,14.22) 105.92,8.64 106.43,8.13 120.65,8.13 122.33,6.45 122.33,4.86 J16.6
AM437X_EHRPWM0_SYNCO: length 150.9
  TOP w0.13: v1(74.63,66.32) 74.63,66.04 74.64,66.04 U11.D11 ; v1(56.43,28.6) 56.44,28.59 56.44,25.2 57.27,24.36 57.27,21.08 56.21,20.02 56.21,18.54 55.27,17.6 55.27,15.14 55.04,14.91 55.04,10.88 59.77,6.15 62.56,6.15 65.79,2.92 65.79,2.41 66.86,1.34 116.84,1.34 J16.10
  L4_SIG2 w0.13: v1(56.43,28.6) 53.91,31.11 53.91,34.28 51.29,36.9 51.29,40.8 54.74,44.24 54.74,47.02 52.76,49 v1(52.76,51.03)
  BOTTOM w0.13: v1(74.63,66.32) 74.1,65.79 73.2,65.79 72.86,66.13 68.19,66.13 67.72,66.6 67.13,66.6 66.52,67.21 61.11,67.21 60.02,66.12 58.24,66.12 56.77,64.64 56.77,55.04 v1(52.76,51.03)
AM437X_EHRPWM0B: length 120.2
  TOP w0.13: R83.1 89.79,83.82 v1(89.79,83.31) 90.25,82.85 90.25,81.87 88.37,79.99 88.37,77.37 87.65,76.66 87.65,75.4 87.33,75.08 87.33,73.99 U11.AC23
  L4_SIG2 w0.13: J16.4 124.33,4.86 124.33,6.25 122.77,7.8 114.88,7.8 110.74,11.94 110.74,17.3 111.43,17.99 111.43,23.81 111.82,24.2 112.53,24.91 116.48,28.86 116.48,29.37 116.48,33.39 115.36,34.5 115.36,37.79 114.09,39.07 114.09,43.95 113.73,44.31 113.73,50.53 112.88,51.38 112.88,55.5 112.15,56.23 112.15,58.92 109.68,61.39 107.94,61.39 105.19,64.14 103.43,64.14 100.45,67.13 99.99,67.13 98.95,68.17 98.95,69.7 99.2,69.95 99.2,74.05 98.12,75.13 98.12,76.15 97.18,77.09 97.18,77.86 91.47,83.57 90.04,83.57 v1(89.79,83.31)
AM437X_EHRPWM1B: length 110.1
  TOP w0.13: U11.AC25 86.99,75.17 87.42,75.61 87.42,76.75 88.14,77.47 88.14,80.7 v1(89.73,82.3)
  L4_SIG2 w0.13: J16.12 116.33,4.86 116.33,6.86 115.7,7.49 114.68,7.49 110.36,11.81 110.36,17.48 111.11,18.23 111.11,23.93 111.51,24.33 116.17,28.99 116.17,29.24 116.17,32.69 115,33.86 115,36.46 113.85,37.61 113.85,38.87 113.78,38.94 113.78,43.83 113.43,44.18 113.43,44.89 112.28,46.04 112.28,52.02 111.7,52.6 111.7,53.07 112.12,53.5 112.12,55.41 111.09,56.44 111.09,58.48 108.55,61.02 106.29,61.02 103.5,63.81 103.5,63.83 103.31,63.83 100.32,66.82 99.87,66.82 98.64,68.04 98.64,69.83 98.89,70.07 98.89,73.02 97.81,74.1 97.81,75.75 92.71,80.84 92.71,81.8 92.22,82.3 v1(89.73,82.3)
  BOTTOM w0.13: v1(89.73,82.3) 90.55,83.11 R375.1
AM437X_EHRPWM2A: length 126.8
  TOP w0.13: U11.B10 73.03,64.89 67.74,64.89 66.96,64.11 v1(66.27,64.11)
  L4_SIG2 w0.13: v1(66.27,64.11) 65.47,63.31 65.01,63.31 64.32,62.62 64.32,61.86 62.37,59.91 62.37,57.64 61.34,56.61 61.34,54.66 57.41,50.73 57.41,41.8 56.15,40.54 56.15,33.21 57.67,31.69 59.17,31.69 59.5,31.35 59.5,30.34 60.26,29.58 60.26,28.01 63.51,24.76 65.05,24.76 73.94,15.88 73.94,11.82 72.37,10.25 72.37,2.94 72.95,2.36 113.87,2.36 J16.14
AM437X_EHRPWM2B: length 134.3
  TOP w0.13: v1(70.36,6.73) 69.85,7.24 67.95,7.24 66.97,6.26 66.97,3.9 68.39,2.47 111.98,2.47 J16.16 ; U11.A10 67.41,65.2 v1(66.88,64.67)
  L4_SIG2 w0.13: v1(66.88,64.67) 66.14,64.67 65.09,63.62 64.88,63.62 64.02,62.75 64.02,61.99 62.41,60.38 62.22,60.38 60.14,58.3 60.14,55.57 56.03,51.46 56.03,42.97 53.66,40.6 53.66,35.4 54.73,34.33 54.73,31.36 62.39,23.71 62.39,22.93 63.15,22.17 65.2,22.17 69.6,17.77 69.64,17.77 71.49,15.91 71.49,15.91 72.99,14.41 72.99,11.83 71.65,10.49 71.65,9.1 70.36,7.8 v1(70.36,6.73)
AM437X_EHRPWM4A: length 12.5
  TOP w0.13: U11.H25 77.24,75.45 77.4,75.62 77.4,76.9 77.9,77.39 77.9,78.03 77.3,78.63 77.3,81.39 77.57,81.66 77.57,81.89 78.2,82.52 78.2,85.88 R70.1
AM437X_EHRPWM4B: length 85.5
  TOP w0.13: v1(76.96,86.23) 76.96,86.11 77.88,85.19 77.88,82.7 77.26,82.09 77.26,81.79 76.98,81.51 76.98,78.62 77.66,77.94 77.66,77.54 77.17,77.05 77.17,75.72 76.91,75.46 76.91,74.62 77.04,74.5 U11.H24 ; R187.1 44.7,39.62 v1(45.09,39.24)
  L4_SIG2 w0.13: v1(45.09,39.24) 46.99,39.24 48.73,40.98 48.73,50.4 48.57,50.56 48.57,54.16 49.19,54.78 49.19,55.61 49.52,55.95 52.11,55.95 56.79,60.63 59.43,60.63 61.28,62.47 61.28,64.44 64.88,68.04 64.88,71.81 66.69,73.62 72.09,73.62 72.76,74.29 72.76,74.53 74.9,76.68 74.9,78.6 76,79.7 76,81.1 74.14,82.96 74.14,85.32 75.21,86.39 76.81,86.39 v1(76.96,86.23)
AM437X_EHRPWM5A: length 21.3
  TOP w0.13: v1(65.48,65.91) R132.1 ; v1(77.7,72.95) 77.65,73 U11.H22
  L4_SIG2 w0.13: v1(65.48,65.91) 65.48,67.08 65.8,67.41 65.8,71.43 67.07,72.7 72.15,72.7 73.45,74 73.45,74.2 74.07,74.82 76.01,74.82 77.58,73.25 77.58,73.25 77.7,73.12 v1(77.7,72.95)
AM437X_EHRPWM012_TRPZONE: length 142
  TOP w0.13: R74.2 R73.2 v1(82.93,87.25)
  L3_SIG1 w0.13: v1(100.08,87.81) 99.26,87.81 97.6,89.47 91.94,89.47 91.21,88.75 89.56,88.75 88.87,89.43 85.12,89.43 v1(82.93,87.25)
  L4_SIG2 w0.13: J16.8 122.56,2.63 127.85,2.63 128.56,3.34 128.56,13.81 122.81,19.56 122.81,26.26 127.9,31.36 127.9,41.9 127.25,42.55 127.25,50.32 126.64,50.93 126.64,60.29 124.74,62.19 124.74,63.43 125.19,63.88 125.19,64.59 124.21,65.58 124.21,67.09 121.17,70.13 116.54,70.13 114.92,71.74 114.92,74.08 114.34,74.66 105.78,74.66 104.96,75.48 104.77,75.67 103.79,75.67 102.98,76.48 102.98,76.98 101.97,77.98 101.97,78.75 100.16,80.57 100.16,87.73 v1(100.08,87.81)
  BOTTOM w0.13: R383.2 84.33,85.85 v1(82.93,87.25)
AM437X_GPIO_CAM: length 53.9
  TOP w0.13: U11.AD17 87.94,69.44 93.57,69.44 95.16,71.03 95.54,71.03 96.77,72.26 97.79,72.26 98.55,73.02 98.55,73.28 98.2,73.63 98.2,75.57 v1(98.96,76.33)
  L3_SIG1 w0.13: v1(98.96,76.33) 99.62,76.99 102.01,76.99 103.96,78.94 103.96,80.87 107.1,84.01 116.37,84.01 118.87,86.51 120.55,86.51 v1(124.26,90.22)
  BOTTOM w0.13: R350.2 126.87,89.53 124.94,89.53 v1(124.26,90.22)
AM437X_GPIO_IND_LDN: length 10
  TOP w0.13: U11.B14 73.01,68.13 69.03,68.13 66.85,70.31 65.84,70.31 65.36,70.79 65.35,70.79 65.18,70.96 R105.2
AM437X_HDQ: length 119.8
  TOP w0.13: v1(80,82.04) 80,81.91 79.01,80.92 78.7,80.61 78.51,80.61 78.01,80.11 78.01,78.9 78.89,78.03 78.89,76.41 78.89,76.41 78.89,75.9 78.23,75.23 78.23,74.61 U11.K24 ; v1(66.09,66.5) 65.99,66.4 65.99,65.81 64.64,64.47 R138.1 ; R243.1 v1(80.98,10.87)
  L3_SIG1 w0.13: v1(76.05,85.55) 76.05,85.38 75.73,85.06 75.73,84.38 75.09,83.74 69.8,83.74 69.79,83.76 69.31,83.76 66.84,81.28 66.84,79.39 66.31,78.86 66.31,78.15 66.8,77.65 66.8,73.05 67.03,72.82 67.03,68.96 66.09,68.02 v1(66.09,66.5)
  L4_SIG2 w0.13: v1(80.98,10.87) 80.09,9.98 79.17,9.98 78.83,10.32 78.83,11.35 79.45,11.97 79.45,17.48 73.26,23.66 72.73,23.66 68.94,27.46 68.44,27.46 66.68,29.21 66.68,32.17 65.48,33.37 64.62,33.37 63.18,34.81 63.18,36.59 62.55,37.22 62.55,39.86 60.5,41.91 60.5,48.66 64.39,52.55 64.39,53.6 64.93,54.13 64.93,60 68.02,63.09 68.02,65.91 67.44,66.5 v1(66.09,66.5) ; v1(80,82.04) 80,84.23 79.61,84.62 79.61,84.92 79.1,85.43 76.16,85.43 v1(76.05,85.55)
AM437X_I2C0_SCL: length 35.7
  TOP w0.13: U11.Y22 85.41,72.63 v1(85.67,72.63)
  L4_SIG2 w0.13: v1(102.49,84.71) 102.49,81.4 102.3,81.21 102.3,79.26 103.06,78.5 103.06,77.36 103.45,76.97 v1(103.45,76.68)
  BOTTOM w0.13: R424.1 101.85,77.53 102.55,76.83 103.29,76.83 v1(103.45,76.68) ; R424.1 R425.2 ; R424.1 101.08,76.82 98.8,76.82 98.04,76.07 98.04,75.18 95.89,73.02 93.22,73.02 92.71,72.52 91.94,72.52 91.11,73.34 86.92,73.34 86.68,73.1 86.68,73.01 86.45,72.79 85.83,72.79 v1(85.67,72.63) ; R356.2 101.73,85.47 v1(102.49,84.71)
AM437X_I2C0_SDA: length 33.6
  TOP w0.13: v1(87.12,79.68) 87.12,78.97 86.02,77.87 86.02,74.62 U11.AB24
  L4_SIG2 w0.13: v1(102.23,85.85) 100.86,84.48 v1(100.86,80.64)
  BOTTOM w0.13: v1(102.23,85.85) 102.23,85.98 103.12,86.87 103.63,86.87 104.14,87.38 R354.2 ; R419.2 R418.1 101.85,80.01 101.22,80.64 v1(100.86,80.64) 100.33,80.64 99.99,80.99 98.75,80.99 97.01,79.25 93.58,79.25 92.96,79.87 87.31,79.87 v1(87.12,79.68)
AM437X_I2C2_SCL: length 17
  TOP w0.13: v1(87.1,72.92) 86.99,72.81 U11.AC21 ; v1(98.99,75.36) 99.29,75.06 R97.2 R96.1
  BOTTOM w0.13: R430.2 99.19,75.56 v1(98.99,75.36) 95.69,72.06 91.77,72.06 90.91,72.92 v1(87.1,72.92)
AM437X_I2C2_SDA: length 17.8
  TOP w0.13: R100.1 R98.2 98.69,73.91 98.68,73.91 v1(98.67,73.91) ; U11.AB20 v1(86.33,72.36)
  BOTTOM w0.13: R432.2 99.06,73.91 98.69,73.91 98.68,73.91 v1(98.67,73.91) 98.04,73.91 95.76,71.63 91.57,71.63 90.69,72.5 86.47,72.5 v1(86.33,72.36)
AM437X_LCD_AC_BIAS_EN: length 309.3
  TOP w0.13: U11.A24 72.44,74.3 72.27,74.13 69.79,74.13 68.17,75.75 68.17,78.02 68.78,78.64 68.78,81.79 68.64,81.94 68.64,86.51 69.28,87.15 69.28,89.97 71.88,92.58 v1(71.88,92.96) R49.1 ; R8.1 16.13,110.36 v1(16.13,106.93) ; R259.2 114.35,8.33 114.35,2.95 113.57,2.17 68.27,2.17 67.41,3.02 66.19,3.02 60.96,8.25 v1(60.96,9.58)
  L3_SIG1 w0.13: v1(57.53,20.07) 48.39,20.07 45.79,22.67 45.79,33.4 44.2,34.99 39.93,34.99 38.48,36.44 38.48,40.13 v1(40.39,42.04) ; v1(71.88,92.96) 71.26,92.96 69.86,94.36 69.86,96.05 69.95,96.13 69.95,98.07 68.27,99.74 62.44,99.74 61.48,100.71 61.48,101.29 59.88,102.89 47.72,102.89 47.13,102.3 30.57,102.3 29.82,103.05 25.71,103.05 25.23,103.53 22.87,103.53 18.58,107.82 17.02,107.82 v1(16.13,106.93) 16.13,104.4 13.97,102.24 13.97,98.3 11.74,96.07 11.74,87.32 13.2,85.86 13.2,76.84 18.92,71.12 18.92,67.69 20.45,66.17 20.45,64.73 21.35,63.83 22.07,63.83 26.1,59.8 26.1,58.35 30.48,53.98 35.52,53.98 40.03,58.49 v1(40.03,58.52)
  L4_SIG2 w0.13: v1(40.03,58.52) 40.03,55.5 41.78,53.75 41.78,43.43 v1(40.39,42.04)
  BOTTOM w0.13: R341.2 v1(71.88,92.96) ; v1(60.96,9.58) 59.75,8.36 59.31,8.36 59.29,8.38 57.18,8.38 54.41,11.15 54.41,13.23 55.84,14.66 55.84,18.89 57.02,20.07 v1(57.53,20.07)
AM437X_LCD_DATA6: length 139.6
  TOP w0.13: v1(74.34,73.14) 74.26,73.14 73.68,72.55 73.68,72.22 73.98,71.92 U11.C20 ; J16.49 78.33,4.82 78.33,3.4 77.79,2.86 68.61,2.86 67.54,3.94 v1(67.54,5.92)
  L4_SIG2 w0.13: v1(49.73,52.86) 50.47,52.12 50.47,39.26 50.11,38.9 50.11,37.64 51.11,36.64 51.11,30.93 55.36,26.68 57.68,26.68 58.33,26.03 58.33,23.85 59.16,23.02 61.36,23.02 62.86,21.51 64.38,21.51 70.83,15.06 70.83,9.44 69.57,8.18 68.55,8.18 67.54,7.16 v1(67.54,5.92)
  BOTTOM w0.13: v1(49.73,52.86) 48.73,53.86 48.73,79.16 52.1,82.52 56.92,82.52 R406.1 58.17,81.28 64.51,81.28 64.64,81.14 66.04,81.14 66.53,80.66 66.53,79.59 67.47,78.66 67.47,77.08 68.21,76.34 68.21,76.33 68.21,75.53 70.97,72.77 73.97,72.77 74.34,73.14 v1(74.34,73.14)
AM437X_LCD_DATA7: length 24.8
  TOP w0.13: v1(75.67,72.44) 75.67,72.24 75.33,71.9 75.27,71.9 75.04,71.68 75.04,71.29 U11.E19
  BOTTOM w0.13: v1(75.67,72.44) 75.67,72.27 75.06,71.66 74.26,71.66 74.11,71.81 69.65,71.81 65.38,76.07 64.2,76.07 63.87,76.4 62.84,76.4 61.43,77.81 59.88,77.81 59.26,78.44 59.26,79.83 58.32,80.77 R408.1
AM437X_LCD_HSYNC: length 249.1
  TOP w0.13: R260.2 116.33,8.39 116.33,3.05 115.14,1.86 67.28,1.86 v1(66.62,2.51) ; v1(67.82,93.83) 68.24,93.41 68.24,92.77 68.26,92.74 68.26,88.13 68,87.87 67.71,87.87 67.37,87.53 67.37,87.48 67.31,87.42 67.31,78.75 67.37,78.69 v1(67.37,76.25) 67.37,75.89 69.72,73.54 72.58,73.54 U11.A23 ; v1(70.48,92.96) R48.1
  L3_SIG1 w0.13: v1(17.02,107.06) 18.83,107.06 22.67,103.22 25.1,103.22 25.58,102.74 29.69,102.74 30.45,101.99 47.26,101.99 47.85,102.58 58.58,102.58 60.07,101.09 60.07,100.49 61.12,99.44 68.14,99.44 69.64,97.94 69.64,96.26 69.55,96.17 69.55,93.9 v1(70.48,92.96) 69.9,92.38 68.25,92.38 67.82,92.81 v1(67.82,93.83) ; v1(65.56,64.77) 65.94,65.15 66.95,65.15 67.55,65.75 67.55,66.14 67.37,66.32 v1(67.37,76.25)
  L4_SIG2 w0.13: v1(66.62,2.51) 67.64,2.51 68.14,3.01 68.14,6.34 68.85,7.05 68.88,7.05 71.34,9.51 71.34,10.62 71.78,11.06 71.78,15.18 71.19,15.78 71.19,15.78 69.51,17.46 69.48,17.46 65.07,21.86 63.03,21.86 62.04,22.84 62.04,23.61 54.42,31.24 54.42,34.21 52.32,36.3 52.32,39.1 52.44,39.21 52.44,40.96 55.48,44 55.48,51.44 59.83,55.79 59.83,58.43 62.09,60.69 62.28,60.69 63.71,62.11 63.71,64.02 64.46,64.77 v1(65.56,64.77)
  BOTTOM w0.13: R279.2 17.02,111 v1(17.02,107.06) ; R342.2 70.48,93.47 v1(70.48,92.96)
AM437X_LCD_PCLK: length 103.3
  TOP w0.13: R10.2 10.92,109.09 10.92,107.19 11.76,106.35 12.57,106.35 13.41,105.51 13.41,104.7 14.07,104.04 15.65,104.04 17.02,105.41 v1(18.03,105.41) ; v1(65.87,79.53) 66.13,79.27 66.13,77.14 66.71,76.56 66.71,75.89 69.7,72.9 72.59,72.9 U11.A22
  L3_SIG1 w0.13: v1(18.03,105.41) 18.03,105.04 18.61,104.46 20.33,104.46 22.18,102.61 24.85,102.61 26.43,101.03 29.83,101.03 30.18,101.38 47.51,101.38 47.99,101.85 52.79,101.85 54.66,99.99 58.47,99.99 60.59,97.86 60.59,96.95 60.88,96.66 65.74,96.66 66.13,97.05 66.13,97.46 67.5,98.82 67.89,98.82 68.16,98.54 68.16,97.48 66.42,95.74 66.42,93.25 63.75,90.58 63.75,88.22 64.84,87.14 64.84,85.96 65.31,85.48 65.31,81.14 65.59,80.86 65.59,79.81 v1(65.87,79.53)
AM437X_LCD_VSYNC: length 95.7
  TOP w0.13: v1(19.3,105.92) 18.87,106.35 14.18,106.35 13.31,107.22 13.31,108.97 12.45,109.83 R12.1 ; R47.1 v1(68.71,92.96) 68.71,87.01 67.64,85.95 67.64,80.41 67.83,80.22 67.83,75.76 69.75,73.84 72.44,73.84 72.56,73.96 73.03,73.96 U11.B23
  L3_SIG1 w0.13: v1(68.71,92.96) 68.71,93.85 69.13,94.27 69.13,96.19 69.33,96.39 69.33,97.81 68.01,99.13 59.98,99.13 58.54,100.57 58.54,101.22 57.56,102.2 47.9,102.2 47.39,101.68 30.32,101.68 29.57,102.44 25.46,102.44 24.98,102.91 24.98,102.92 22.31,102.92 v1(19.3,105.92)
  BOTTOM w0.13: R47.1 v1(68.71,92.96)
AM437X_MCASP0_ACLKR: length 189.2
  TOP w0.13: v1(79.72,73.82) 79.55,73.65 U11.L23 ; R251.1 95.76,9.4 v1(96.7,8.46)
  L4_SIG2 w0.13: v1(96.7,8.46) 97.51,7.65 101.82,7.65 104.97,10.8 104.97,13.19 104.38,13.79 104.38,19.25 105.2,20.07 105.2,21.92 105.91,22.63 105.91,23.55 105.32,24.15 105.32,24.96 105.64,25.29 105.64,26.02 105.34,26.32 105.34,34.94 105.06,35.23 105.06,37.35 105.06,43.13 103,45.18 103,49.75 101.3,51.45 101.3,51.96 101.3,51.96 101.3,52.83 100.02,54.11 100.02,56.28 99.2,57.1 99.2,58.62 98.89,58.94 98.89,58.94 94.78,63.05 94.78,63.88 92.58,66.08 92.58,70.4 90.13,72.85 89.91,72.85 87.7,75.06 86.05,75.06 81.03,80.08 81.03,81.57 80.88,81.72 80.88,83.17 81.15,83.44 v1(81.15,85.22)
  BOTTOM w0.13: v1(79.72,73.82) 79.72,81.09 80.5,81.87 80.5,82.82 81.15,83.47 v1(81.15,85.22) ; v1(96.7,8.46) 96.01,9.14 71.65,9.14 70.86,8.35 67.3,8.35 65.64,6.69 63.62,6.69 63.18,7.13 56.5,7.13 51.54,12.09 44.3,12.09 39.34,17.05 39.34,21.72 37.56,23.49 34.8,23.49 32.14,26.15 U58.3
AM437X_MCASP0_AHCLKR: length 89.7
  TOP w0.13: v1(102.51,10.41) 101.5,9.4 R252.1 ; v1(80.23,78.9) 80.23,75.89 79.52,75.18 79.52,74.62 U11.M24
  L4_SIG2 w0.13: v1(80.23,78.9) 80.26,78.9 84.79,74.37 87.17,74.37 91.66,69.88 91.66,65.7 93.86,63.5 93.86,62.66 97.36,59.16 97.36,56.31 99.03,54.64 99.03,53.79 100.37,52.45 100.37,51.07 102.08,49.36 102.08,44.8 102.86,44.02 104.13,42.75 104.13,37.74 104.13,34.85 104.29,34.69 104.29,26.87 103.57,26.15 103.57,24.59 103.88,24.28 103.88,20.06 103.37,19.55 103.37,13.34 103.21,13.17 103.21,12.4 103.44,12.17 103.44,11.34 v1(102.51,10.41)
AM437X_MCASP0_AHCLKX: length 155.1
  TOP w0.13: R240.1 75.79,10.82 75.03,10.82 74.42,11.43 74.42,12.9 69.31,18.02 67.04,18.02 v1(66.8,17.78) ; v1(78.66,79.65) 79.52,78.79 79.52,75.84 78.87,75.19 78.87,74.62 U11.L24
  L3_SIG1 w0.13: v1(66.8,17.78) 66.42,18.16 61.73,18.16 60.58,17.01 54.99,17.01 52.67,19.33 46.69,19.33 43.42,22.6 43.42,29.22 43.24,29.4 43.24,33.97 42.55,34.67 38.1,34.67 36.7,36.07 v1(36.7,37.97)
  L4_SIG2 w0.13: v1(78.66,79.65) 77.42,79.65 75.52,77.75 75.52,76.64 73.22,74.34 73.22,74.1 72.13,73.01 66.95,73.01 65.49,71.55 65.49,67.78 64.85,67.13 64.85,65.59 63.4,64.14 63.4,62.24 62.16,61 61.72,61 60.73,60.01 57.12,60.01 51.63,54.52 51.63,53.86 51.29,53.53 49.74,53.53 49.19,52.98 49.19,51.2 49.35,51.03 49.35,38.88 48.47,38 46.21,38 44.17,35.95 44.17,35.63 43.42,34.88 38.31,34.88 36.7,36.49 v1(36.7,37.97)
  BOTTOM w0.13: U58.6 34.09,28.7 34.92,29.54 34.92,36.2 v1(36.7,37.97)
AM437X_MCASP0_AXR1: length 176.4
  TOP w0.13: v1(80.47,80.59) 80.47,79.4 80.67,79.2 80.67,76.01 79.83,75.17 U11.M25 ; R242.1 78.36,12.32 77.89,12.79 74.97,12.79 69.44,18.33 66.71,18.33 v1(65.79,17.4)
  L3_SIG1 w0.13: v1(65.79,17.4) 61.94,17.4 60.28,15.74 55.82,15.74 52.77,18.8 46.79,18.8 46.28,19.3 43.12,22.47 43.12,28.77 41.78,30.1 41.78,33.73 41.15,34.36 37.97,34.36 36.23,36.1 36.23,38.39 v1(36.83,38.99)
  L4_SIG2 w0.13: v1(36.83,38.99) 37.46,38.35 37.46,37.46 39.74,35.19 43.29,35.19 43.86,35.75 43.86,36.08 46.09,38.31 48.34,38.31 49.04,39.01 49.04,50.53 48.88,50.69 48.88,54.03 49.52,54.68 51.33,54.68 56.97,60.32 60.6,60.32 61.59,61.31 62.03,61.31 62.43,61.71 62.43,65.15 65.19,67.91 65.19,71.68 66.82,73.31 72.11,73.31 72.99,74.19 72.99,74.44 75.21,76.66 75.21,78.39 76.31,79.49 76.31,81.23 74.5,83.04 74.5,85.19 75.34,86.03 76.38,86.03 76.66,85.74 79.97,85.74 80.51,85.21 80.66,85.05 80.66,84.62 80.48,84.44 80.48,80.6 v1(80.47,80.59)
  BOTTOM w0.13: v1(36.83,38.99) 34.62,36.78 34.62,29.88 33.44,28.7 U58.5
AM437X_MCASP0_FSR: length 185.6
  TOP w0.13: R250.1 93.73,10.03 91.69,10.03 91.06,10.67 v1(87.88,10.67) ; U11.K23 78.19,73.99 77.79,73.99 v1(77.67,73.87)
  L4_SIG2 w0.13: v1(70.48,91.95) 70.48,88.28 68.64,86.44 68.64,85.78 65.09,82.23 65.09,80.29 64.76,79.96 64.76,75.18 62.89,73.32 62.41,73.32 61.1,72.01 61.1,70.08 57.76,66.74 50.07,66.74 50.07,66.74 47.49,66.74 39.55,58.8 39.55,55.55 41.4,53.69 41.4,49.53 35.66,43.79 35.66,40.09 v1(34.31,38.73)
  BOTTOM w0.13: v1(70.48,91.95) 70.48,90.17 74.59,86.07 74.59,84.82 75.31,84.09 75.31,82.2 77.62,79.9 77.62,79.45 77.63,79.43 77.63,77.23 77.35,76.95 77.35,75.17 77.67,74.85 v1(77.67,73.87) ; v1(34.31,38.73) 34.31,30 32.79,28.49 U58.4 32.79,26.26 35.18,23.88 37.62,23.88 39.65,21.84 39.65,17.5 44.68,12.47 51.66,12.47 56.7,7.44 63.31,7.44 63.75,7 65.31,7 66.97,8.65 70.68,8.65 71.52,9.49 82.51,9.49 82.98,9.96 87.17,9.96 v1(87.88,10.67)
AM437X_MMC0_CLK: length 18.7
  TOP w0.13: v1(73.33,57.93) 74.18,57.93 74.64,58.38 U11.D1 ; R179.2 64.67,50.32 64.67,51.81 67.59,54.74 67.82,54.74 v1(68.07,54.99)
  L4_SIG2 w0.13: v1(68.07,54.99) 68.58,54.48 71.81,54.48 73.05,55.73 73.05,57.65 v1(73.33,57.93)
AM437X_MMC0_CMD: length 19.1
  TOP w0.13: v1(67.36,55.12) 64.21,51.97 64.21,51 R177.2 ; v1(74.01,58.35) 74.29,58.63 74.29,59.66 U11.D2
  L4_SIG2 w0.13: v1(67.36,55.12) 67.36,54.82 68.13,54.05 72.08,54.05 74.01,55.97 v1(74.01,58.35)
AM437X_MMC0_DAT0: length 86.3
  TOP w0.13: U11.C1 73.98,58.92 73.44,58.38 v1(72.89,58.38) ; v1(72.39,12.32) R238.1 ; v1(68.07,55.75) 67.38,55.75 63.75,52.13 63.75,51.69 R174.2
  L4_SIG2 w0.13: v1(81.69,11.46) 81.69,16.61 73.66,24.63 73.16,24.63 69.73,28.06 69.6,28.06 69.3,28.36 68.7,28.97 68.7,29.9 67.56,31.04 67.56,32.46 67.49,32.54 67.49,32.74 66.32,33.91 66.32,39.42 65.36,40.37 63.41,40.37 61.47,42.31 61.47,48.24 66.04,52.81 66.04,55.12 66.67,55.75 v1(68.07,55.75) 68.69,55.75 69.52,54.92 71.58,54.92 72.59,55.93 72.59,58.08 v1(72.89,58.38)
  BOTTOM w0.13: v1(81.69,11.46) 79.62,11.46 79.24,11.08 74.52,11.08 73.79,11.81 72.9,11.81 v1(72.39,12.32)
AM437X_MMC0_DAT1: length 88.6
  TOP w0.13: v1(67.95,56.52) 67.31,56.52 63.25,52.45 R167.2 62.69,52.88 v1(58.78,52.88) ; U11.C2 73.64,59.66 73.64,59.22 v1(73.26,58.84) ; R249.1 91.57,9.4 90.93,10.03 87.63,10.03 86.29,11.37 82.81,11.37 80.86,13.33 75.47,13.33 73.08,15.72 v1(73,15.72)
  L4_SIG2 w0.13: v1(67.95,56.52) 68.33,56.9 68.33,57.91 69.26,58.84 v1(73.26,58.84) ; v1(58.78,52.88) 56.87,50.98 56.87,42.02 55.61,40.76 55.61,31.91 56.84,30.67 58.02,30.67 58.36,30.34 58.36,29.16 60.93,26.59 63.29,24.22 64.5,24.22 v1(73,15.72)
AM437X_MMC0_DAT2: length 145.3
  TOP w0.13: R161.2 63.5,53.47 64.01,53.98 64.01,53.98 v1(64.39,54.36) 64.39,54.36 65.37,55.34 65.63,55.34 67.22,56.94 67.86,56.94 68.1,57.18 68.1,57.81 68.33,58.04 68.33,58.21 69.3,59.18 69.65,59.18 70.67,60.2 71.97,60.2 72.48,59.69 73.03,59.69 U11.B2 ; v1(51.18,48.77) 50.16,47.75 50.16,45.99 45.5,41.33 35.74,41.33 v1(32.13,37.72)
  L4_SIG2 w0.13: v1(64.39,54.36) 63.83,53.8 63.83,52.76 59.96,48.89 59.96,40.91 60.98,39.9 60.98,38.44 61.8,37.62 61.8,35.44 64.4,32.83 65.26,32.83 66.14,31.95 66.14,28.99 68.08,27.05 68.58,27.05 72.78,22.85 72.78,20.33 75.59,17.52 77.75,17.52 78.91,16.36 78.91,12.19 78.3,11.58 78.3,10.09 79.25,9.14 v1(79.25,7.42)
  BOTTOM w0.13: J16.37 90.12,7.07 86.12,7.07 85.92,6.87 83.75,6.87 83.2,7.42 v1(79.25,7.42) ; v1(51.18,48.77) 58.7,48.77 64.29,54.36 v1(64.39,54.36) ; v1(32.13,37.72) 23.76,37.72 R514.2
